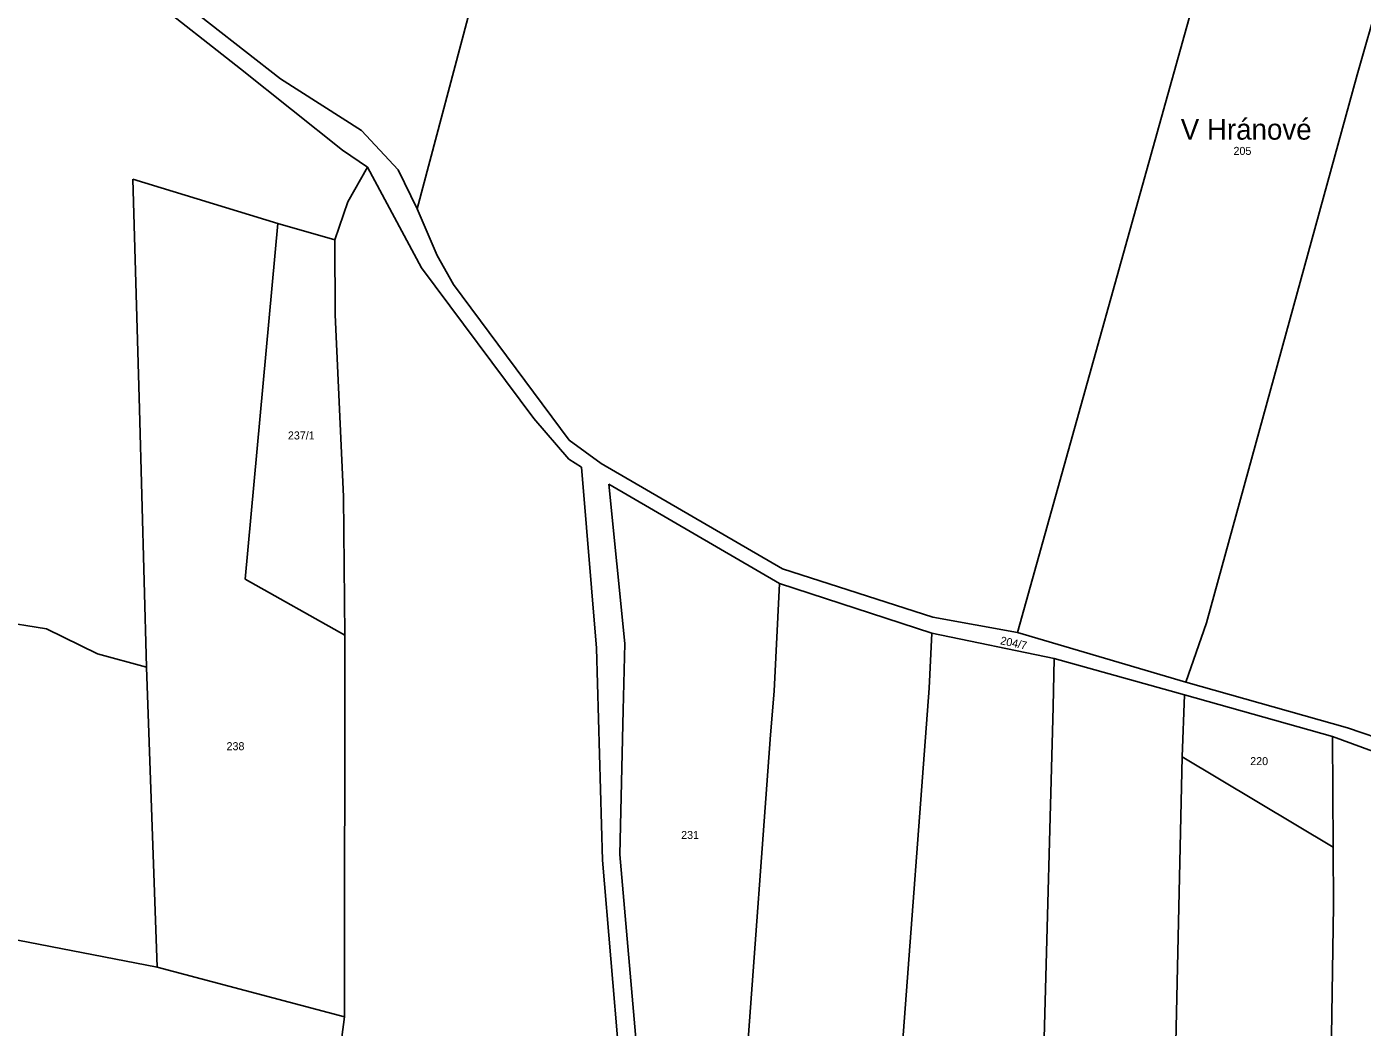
# Model space of a CAD drawing. Extents: x -791548 to -789311, y -1142631 to -1140855.
# Drawn here: x -790661.5 to -790377.8, y -1141741.3 to -1141528.8 of the extents above; entities that cross this region are included whole.
import ezdxf
from ezdxf.enums import TextEntityAlignment as Align

# ---------------------------------------------------------------- set-up
doc = ezdxf.new("R2010")
doc.units = 0
doc.header["$LTSCALE"] = 0.68
doc.layers.add('1', color=7, linetype='Continuous', lineweight=25)
doc.layers.add('7', color=7, linetype='Continuous', lineweight=13)
doc.layers.add('2', color=7, linetype='Continuous')

msp = doc.modelspace()

# ---------------------------------------------------------------- linework, layer by layer
at = {"layer": '1'}
for p, q in [((-790378.88, -1141539.02), (-790345.36, -1141422.16)), ((-790578.57, -1141567.47), (-790557.94, -1141489.62)), ((-790616.11, -1141537.74), (-790661.03, -1141502.45)), ((-790607.61, -1141539.86), (-790638.34, -1141515.86)), ((-790451.05, -1141657.46), (-790413.68, -1141523.93)), ((-790594.46, -1141555.01), (-790616.11, -1141537.74)), ((-790410.84, -1141655.41), (-790378.88, -1141539.02)), ((-790590.41, -1141550.87), (-790607.61, -1141539.86)), ((-790582.61, -1141559.23), (-790590.41, -1141550.87)), ((-790589.11, -1141558.65), (-790594.46, -1141555.01)), ((-790589.11, -1141558.65), (-790593.32, -1141565.99)), ((-790577.66, -1141580.03), (-790589.11, -1141558.65)), ((-790578.57, -1141567.47), (-790582.61, -1141559.23)), ((-790637.56, -1141610.02), (-790638.96, -1141561.17)), ((-790608.17, -1141570.57), (-790638.96, -1141561.17)), ((-790593.32, -1141565.99), (-790596.05, -1141574.05)), ((-790574.35, -1141577.36), (-790578.57, -1141567.47)), ((-790608.17, -1141570.57), (-790615.14, -1141646.1)), ((-790608.17, -1141570.57), (-790596.05, -1141574.05)), ((-790596.05, -1141574.05), (-790596.01, -1141590.02)), ((-790570.83, -1141583.55), (-790574.35, -1141577.36)), ((-790553.78, -1141611.99), (-790577.66, -1141580.03)), ((-790546.28, -1141616.6), (-790570.83, -1141583.55)), ((-790596.01, -1141590.02), (-790594.2, -1141628.54)), ((-790636.08, -1141664.82), (-790637.56, -1141610.02)), ((-790546.38, -1141620.64), (-790553.78, -1141611.99)), ((-790539.49, -1141621.58), (-790546.28, -1141616.6)), ((-790543.66, -1141622.33), (-790546.38, -1141620.64)), ((-790500.97, -1141643.94), (-790539.49, -1141621.58)), ((-790540.45, -1141660.75), (-790543.66, -1141622.33)), ((-790537.86, -1141625.94), (-790501.58, -1141647.05)), ((-790534.42, -1141659.79), (-790537.86, -1141625.94)), ((-790593.95, -1141658.05), (-790594.2, -1141628.54)), ((-790469.05, -1141654.19), (-790500.97, -1141643.94)), ((-790593.95, -1141658.05), (-790615.14, -1141646.1)), ((-790502.72, -1141669.92), (-790501.58, -1141647.05)), ((-790501.58, -1141647.05), (-790469.24, -1141657.6)), ((-790678, -1141653.37), (-790657.29, -1141656.65)), ((-790451.05, -1141657.46), (-790469.05, -1141654.19)), ((-790410.84, -1141655.41), (-790415.27, -1141668.01)), ((-790657.29, -1141656.65), (-790646.52, -1141661.95)), ((-790594, -1141739.05), (-790593.95, -1141658.05)), ((-790469.24, -1141657.6), (-790469.79, -1141669.3)), ((-790443.22, -1141662.95), (-790469.24, -1141657.6)), ((-790415.27, -1141668.01), (-790451.05, -1141657.46)), ((-790539.17, -1141705.76), (-790540.45, -1141660.75)), ((-790534.83, -1141673.97), (-790534.42, -1141659.79)), ((-790646.52, -1141661.95), (-790636.08, -1141664.82)), ((-790443.22, -1141662.95), (-790443.43, -1141673.24)), ((-790415.54, -1141670.71), (-790443.22, -1141662.95)), ((-790633.79, -1141728.5), (-790636.08, -1141664.82)), ((-790502.72, -1141669.92), (-790503.5, -1141679.2)), ((-790476.81, -1141762.76), (-790469.79, -1141669.3)), ((-790415.27, -1141668.01), (-790380.92, -1141677.66)), ((-790416.01, -1141683.85), (-790415.54, -1141670.71)), ((-790415.54, -1141670.71), (-790384.14, -1141679.55)), ((-790535.49, -1141704.61), (-790534.83, -1141673.97)), ((-790445.38, -1141743.56), (-790443.43, -1141673.24)), ((-790380.92, -1141677.66), (-790359.58, -1141685.03)), ((-790503.5, -1141679.2), (-790509.62, -1141762.56)), ((-790360.38, -1141688.22), (-790384.14, -1141679.55)), ((-790384.14, -1141679.55), (-790383.94, -1141703.03)), ((-790417.57, -1141751.89), (-790416.01, -1141683.85)), ((-790383.94, -1141703.03), (-790416.01, -1141683.85)), ((-790383.94, -1141703.03), (-790383.87, -1141715.51)), ((-790534.08, -1141766.65), (-790539.17, -1141705.76)), ((-790531.61, -1141749.58), (-790535.49, -1141704.61)), ((-790383.87, -1141715.51), (-790384.67, -1141762.39)), ((-790682.89, -1141719.09), (-790633.79, -1141728.5)), ((-790594, -1141739.05), (-790633.79, -1141728.5)), ((-790602.93, -1141804.46), (-790594, -1141739.05))]:
    msp.add_line(p, q, dxfattribs=at)

# ---------------------------------------------------------------- texts
at = {"layer": '2'}
for s, p in [('205', (-790403.239, -1141556.032)), ('237/1', (-790603.19, -1141616.452)), ('238', (-790617.169, -1141682.442)), ('220', (-790399.689, -1141685.612)), ('231', (-790520.589, -1141701.292))]:
    msp.add_text(s, height=1.7, dxfattribs=at).set_placement(p, align=Align.CENTER)
msp.add_text('204/7', height=1.7, rotation=348, dxfattribs=at).set_placement((-790452.0057, -1141660.5138), align=Align.CENTER)
at = {"layer": '7'}
msp.add_text('V Hránové', height=4.4, dxfattribs=at).set_placement((-790402.44, -1141552.79), align=Align.CENTER)

doc.saveas('drawing.dxf')
